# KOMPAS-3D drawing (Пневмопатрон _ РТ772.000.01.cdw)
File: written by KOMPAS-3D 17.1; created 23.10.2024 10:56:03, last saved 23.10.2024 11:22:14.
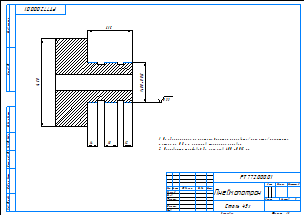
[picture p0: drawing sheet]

Sheet 1: A3, landscape

Title block, sheet 1: name: Пневмопатрон; designation: РТ772.000.01; material: Сталь 45х; sheets: 1; sheet format: A3

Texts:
  Asus
  1. На обозначенные на чертеже участки наплавить/напылить/наростить
  металл на 0,8 мм, заполнив тормозные канавки.
  2. Произвести шлифовку до размеров 400 -0,015 мм
Dimensions and other numbers on the sheet: 14; 18; 12; -0,015; 400; 61,5; 0,33; 450; 1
